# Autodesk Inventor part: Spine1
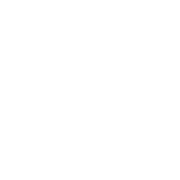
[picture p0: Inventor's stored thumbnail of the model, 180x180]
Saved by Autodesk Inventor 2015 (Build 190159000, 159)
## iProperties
Created: 2016-02
Part Number: Spine1
Material: Wood (Birch)
Document SubType Name: Modeling
Designer: Hafliði
Density: 0.55 g/cm^3
Appearance: Birch - Natural Polished
Mass: 3580.5 g
Surface Area: 2938 cm^2
Volume: 6510 cm^3
Author: Hafliði
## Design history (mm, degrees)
sketch "Sketch2"
  geometry: L1 (-35, 75)-(35, 75); L2 (35, 75)-(35, -75); L3 (35, -75)-(-35, -75); L4 (-35, -75)-(-35, 75); L5 (-35, 75)-(35, -75); L6 (35, 75)-(-35, -75); 1 further point
  constraints: 12 end point, 2 midpoint, 2 parallel, 1 horizontal, 1 perpendicular
  dimensions: "d0" = 70 distance of L2.end L3.end; "d1" = 150 distance of L1.end L2.end
extrude "Extrusion1" new body sketch "Sketch2" distance "d2" = 620; taper "d3" = 0 deg
body "Solid1"
